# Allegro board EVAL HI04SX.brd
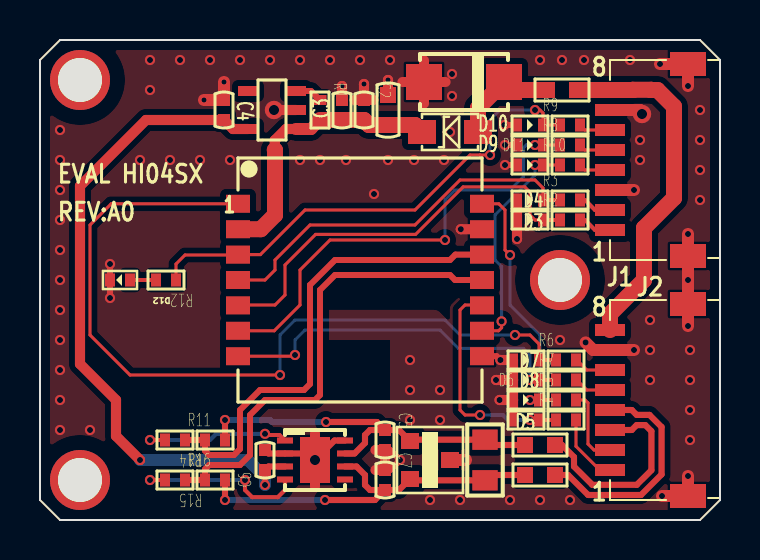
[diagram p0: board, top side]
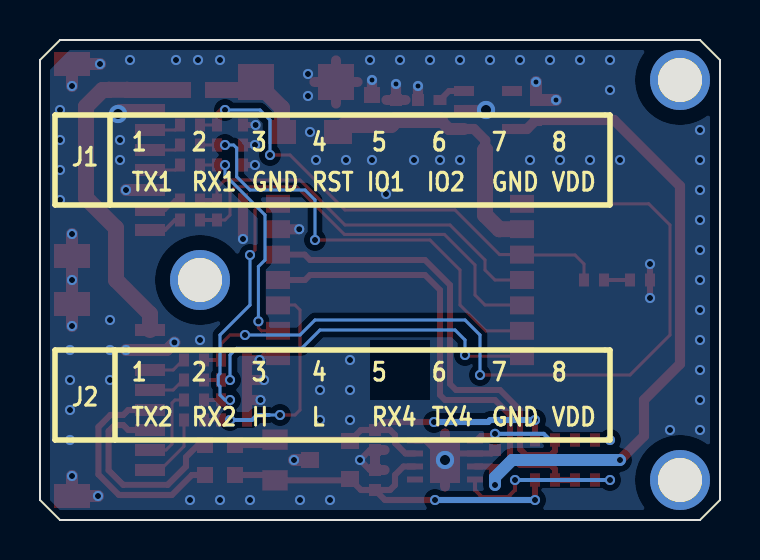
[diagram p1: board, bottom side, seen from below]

Outline 34 x 24 mm; copper layers: TOP, BOTTOM. Coordinates in mm from the lower left corner of the outline.
Outline path: 0,23 0,1 1,0 33,0 34,1 34,23 33,24 1,24 0,23

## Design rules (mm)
constraint set DEFAULT: min track width 0.152
net group CAN2: nets H L

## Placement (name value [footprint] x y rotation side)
C1  10uF  [C0603]  17.4 20.5 270 top
C2  0.1uF  [C0402]  16.2 20.5 270 top
C3  1uF  [C0402]  15.1 20.5 90 top
C4  1uF  [C0402]  9.2 20.5 270 top
C5  100pF  [C0402]  17.25 4 270 top
C6  0.1uF  [C0402]  11.25 3 90 top
C7  100pF  [C0402]  17.25 2 270 top
D1  RB160MM-60TR  [SOD123FL]  20.5 19.4 0 top
D2  SDD32A05L01  [DO-214AC]  21.2 21.9 180 top
D3  SBD52C05L01  [SOD-523]  24.5 15 0 top
D4  SBD52C05L01  [SOD-523]  24.5 16 0 top
D5  SBD52C05L01  [SOD-523]  24.3 5 0 top
D6  SBD52C05L01  [SOD-523]  24.3 6 0 top
D7  SBD52C05L01  [SOD-523]  24.3 8 0 top
D8  SBD52C05L01  [SOD-523]  24.3 7 0 top
D9  SBD52C05L01  [SOD-523]  24.5 18.75 0 top
D10  SBD52C05L01  [SOD-523]  24.5 19.75 0 top
D11  SBD52C05L01  [SOD-523]  24.5 17.75 0 top
D12  GREEN  [LED0402]  4 12 180 top
D13  SM24CANB-02HTG  [SOT23-3-0_95]  19.5 3 270 top
F1  100mA  [F0603]  25 3.75 180 top
F2  100mA  [F0603]  25 2.25 180 top
F3  300mA  [F0603]  26.1 21.5 180 top
H1  HOLE  [HOLE-2-MM]  2 22 0 top
H2  HOLE  [HOLE-2-MM]  2 2 0 top
H3  HOLE  [HOLE-2-MM]  26 12 0 top
J1  CON10  [5015680807_1]  28.5 18 270 top
J2  CON10  [5015680807_1]  28.5 6 270 top
R1  1K  [R0402]  14 20.5 270 top
R2  33R  [R0402]  26.5 15 0 top
R3  33R  [R0402]  26.5 16 0 top
R4  33R  [R0402]  26.3 5 0 top
R5  33R  [R0402]  26.3 6 0 top
R6  33R  [R0402]  26.3 8 0 top
R7  33R  [R0402]  26.3 7 0 top
R8  33R  [R0402]  26.5 18.75 0 top
R9  33R  [R0402]  26.5 19.75 0 top
R10  33R  [R0402]  26.5 17.75 0 top
R11  0R  [R0402]  8.75 4 0 top
R12  1K  [R0402]  6.3 12 180 top
R13  120R/DNP  [R0805]  22.25 3 90 top
R14  1K  [R0402]  6.75 4 180 top
R15  1K  [R0402]  6.75 2 180 top
R16  0R  [R0402]  8.75 2 0 top
U1  SPX3819M5-L-3-3/TR  [SOT23-5-0_95]  11.6 20.5 90 top
U2  HI04SX  [HI04XX]  16 12 0 top
U3  SIT3051TK  [HVSON8]  13.75 3 0 top

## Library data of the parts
C1-C7 = Capacity_Nonpolarity
D1 = diode
D2-D11 = DIODE BI-DIR TRIG
D12 = LED
D13 = BAT54A/SOT
F1-F3 = Fuse
H1-H3 = HOLE
J1 J2 = CON10
R1-R16 = Res
U1 = XC6210
U2 = HI04SX
U3 = SIT3051TK

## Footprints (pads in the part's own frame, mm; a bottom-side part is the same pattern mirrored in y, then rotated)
5015680807_1
  rect 0.6x1.5 smd: 1(3.5,0) 2(2.5,0) 3(1.5,0) 4(0.5,0) 5(-0.5,0) 6(-1.5,0) 7(-2.5,0) 8(-3.5,0)
  rect 1.2x1.8 smd: 9(4.8,3.9) 10(-4.8,3.9)
C0402
  rect 0.6x0.6 smd: 1(-0.5,0) 2(0.5,0)
C0603
  rect 0.8x0.8 smd: 1(-0.75,0) 2(0.75,0)
DO-214AC
  rect 1.8x1.8 smd: 1(2,0) 2(-2,0)
F0603
  rect 0.8x0.8 smd: 1(-0.75,0) 2(0.75,0)
HI04XX
  rect 1.2x0.9 smd: 1(-6.1,3.81) 2(-6.1,2.54) 3(-6.1,1.27) 4(-6.1,0) 5(-6.1,-1.27) 6(-6.1,-2.54) 7(-6.1,-3.81) 8(6.1,-3.81) 9(6.1,-2.54) 10(6.1,-1.27) 11(6.1,0) 12(6.1,1.27) 13(6.1,2.54) 14(6.1,3.81)
HOLE-2-MM
  round 3 hole 2.2: 1(0,0)
HVSON8
  rect 0.8x0.3 smd: 1(-1.5,0.975) 2(-1.5,0.325) 3(-1.5,-0.325) 4(-1.5,-0.975) 5(1.5,-0.975) 6(1.5,-0.325) 7(1.5,0.325) 8(1.5,0.975)
  rect 1.5x2.3 smd: 9(0,0)
LED0402
  rect 0.5x0.65 smd: 1(-0.5,0) 2(0.5,0)
R0402
  rect 0.5x0.65 smd: 1(-0.5,0) 2(0.5,0)
R0805
  rect 1.016x1.27 smd: 1(-1.016,0) 2(1.016,0)
SOD123FL
  rect 1.4x1.2 smd: 1(1.4,0) 2(-1.4,0)
SOD-523
  rect 0.5x0.65 smd: 1(-0.65,0) 2(0.65,0)
SOT23-3-0_95
  rect 0.8x0.9 smd: 1(-0.95,-1) 2(0.95,-1) 3(0,1)
SOT23-5-0_95
  rect 0.5x1 smd: 1(-0.95,-1.2) 2(0,-1.2) 3(0.95,-1.2) 4(0.95,1.2) 5(-0.95,1.2)

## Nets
GND: C1.1 C2.1 C3.2 C4.1 C5.2 C6.2 C7.1 D2.1 D3.1 D4.1 D5.1 D6.1 D7.1 D8.1 D9.1 D10.1 D11.1 D12.2(-) D13.3 J1.3 J1.7 J1.9 J1.10 J2.7 J2.9 J2.10 U1.2(VSS) U2.8 U2.13 U3.2 U3.8 U3.9
VCC: F3.1 J1.8 J2.8
VDD: C1.2 C2.2 C3.1 D1.2 R1.2 U1.1 U2.2(VDD)
CAN_RX/L: R15.1 R16.1 U2.11
CAN_TX/H: R11.1 R14.1 U2.12
DP3V3: C4.2 C6.1 U1.5 U3.3(VCC)
H: F1.1 J2.3
IO1: D9.2 R8.1 U2.6
IO2: D10.2 R9.1 R12.1 U2.3
IO_1: J1.5 R8.2
IO_2: J1.6 R9.2
L: F2.1 J2.4
NRST: J1.4 R10.2
RST: D11.2 R10.1 U2.9
RXD1: D4.2 R3.1 U2.4
RXD2: D6.2 R5.1 U2.14
RXD4: D8.2 R7.1 U2.7
TXD1: D3.2 R2.1 U2.5
TXD2: D5.2 R4.1 U2.10
TXD4: D7.2 R6.1 U2.1
USART1_RX: J1.2 R3.2
USART1_TX: J1.1 R2.2
USART2_RX: J2.2 R5.2
USART2_TX: J2.1 R4.2
USART4_RX: J2.5 R7.2
USART4_TX: J2.6 R6.2
N2198535: D12.1 R12.2
N2224750: R1.1 U1.3
N2242059: C5.1 D13.1 F1.2 R11.2 R13.2 U3.7
N2242241: R14.2 U3.1
N2242331: C7.2 D13.2 F2.2 R13.1 R16.2 U3.6
N2242381: R15.2 U3.4
N2269430: D1.1(P) D2.2 F3.2

Pads without a net: H1 1; H2 1; H3 1; U1 4; U3 5

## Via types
v1: diameter 0.508, hole 0.305, TOP to BOTTOM, 110 vias
v2: diameter 0.508, hole 0.254, TOP to BOTTOM, 5 vias
v3: diameter 0.914, hole 0.508, TOP to BOTTOM, 3 vias

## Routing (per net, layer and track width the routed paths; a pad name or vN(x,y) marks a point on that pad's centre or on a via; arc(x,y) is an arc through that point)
GND: length 50
  TOP w0.3: v1(23.02,8) 22.83,8.19 U2.8 ; D9.1 v1(23.25,18.75) ; D10.1 v1(23.22,19.75) ; D11.1 v1(23.25,17.75)
  TOP w0.305: C5.2 17.5,3.5 v1(18,3) 17.5,2.5 C7.1 ; U3.8 14.72,3.97 v3(13.75,3) 13.43,3.32 U3.2 11.43,3.32 C6.2 ; v1(3.5,11.1) D12.2 v1(3.5,12.8)
  TOP w0.5: 18.12,21.9 D2.1 ; D2.1 20.28,21.9 ; D2.1 19.2,22.98 ; D2.1 19.2,20.82 ; 13.75,1.67 v3(13.75,3) 13.75,4.33 ; 15.72,21 C2.1 16.68,21 ; 17.25,2.98 C7.1 16.77,2.5 ; 16.77,3.5 C5.2 17.25,3.02
  TOP w0.508: D5.1 D6.1 ; D6.1 v1(22.98,6) ; D6.1 D8.1 ; D8.1 v1(22.8,7) ; D8.1 D7.1 v1(23.02,8) ; C3.2 v2(15.1,21.7) ; U1.2 v3(11.7,20.5) ; v1(23.85,14.05) D3.1 D4.1 ; U2.13 v1(21.04,14.54) ; C1.1 v2(17.4,22) ; C2.1 v2(16.2,21.8)
  TOP w0.6: v1(31,22.8) J1.10 v1(32.4,21.7) ; v2(9.2,21.9) C4.1 v2(8.2,21) ; v3(30.1,20.3) 30.1,20.4 30,20.5 J1.7 ; v1(32.4,14.3) J1.9 v1(32.4,12) J2.10 v1(32.4,9.7) ; v1(31.1,1.2) J2.9 v1(32.4,2.2) ; v1(27.28,8.88) 27.66,8.5 J2.7 v1(29.7,8.5) ; J1.3 v1(29.7,16.5) ; D13.3 v1(21.3,3)
  vias: v1(1,19.5) v1(1,18) v1(1,16.5) v1(1,15) v1(1,13.5) v1(1,12) v1(1,10.5) v1(1,9) v1(1,7.5) v1(1,6) v1(1,4.5) v1(2.5,4.5) v1(5,18) v1(5.5,23) v1(5.5,21.5) v1(6.5,18) v1(7,23) v1(8,18) v1(8.5,23) v1(9.5,18) v1(10,23) v1(11.5,23) v1(13,23) v1(13,18) v1(14,18) v1(14.5,23) v1(15.3,18) v1(16,23) v1(16.7,16.3) v1(17.4,18) v1(17.5,23) v1(18.5,8) v1(18.5,6.5) v1(18.5,5) v1(18.7,18) v1(19.5,1) v1(20,6.5) v1(20,5) v1(20.2,18) v1(20.5,19.4) v1(20.6,22.3) v1(20.6,21.2) v1(21,1) v1(23.5,1) v1(25,23) v1(25,1) v1(26,9) v1(26.1,23) v1(26.5,1) v1(27.2,23) v1(29.5,23) v1(30,19) v1(30,18) v1(30.5,10) v1(30.5,8.5) v1(30.5,7) v1(32.5,8.5) v1(32.5,7) v1(32.5,5.5) v1(32.5,4) v1(33,20.5) v1(33,19) v1(33,17.5) v1(33,16)
VCC: length 17.7
  TOP w0.8: J2.8 28.5,10.3 30.2,12 30.2,14.6 31.7,16.1 31.7,20.67 30.87,21.5 30.57,21.5 30.56,21.51 29.64,21.51 29.63,21.5 J1.8 F3.1
VDD: length 13.9
  TOP w0.508: 11.74,18.5 11.74,18.99 12.3,19.55 U1.1
  TOP w0.6: U1.1 13.55,19.55 R1.2
  TOP w0.8: D1.2 18.75,19.75 C1.2 16.45,19.75 C2.2 C3.1 R1.2 ; 11.74,18.5 11.75,18.49 11.75,15.25 11.04,14.54 U2.2
CAN_RX/L: length 23.8
  TOP w0.3: U2.11 20.75,12 20.5,12.25 14.75,12.25 14,11.5 14,6.25 13.75,6 11.25,6 10.5,5.25 10.5,3.25 10,2.75 8.46,2.75 8.25,2.54 R16.1
  TOP w0.305: R16.1 R15.1
CAN_TX/H: length 23.7
  TOP w0.3: U2.12 20.77,13.27 20.5,13 14.75,13 13.5,11.75 13.5,6.8 13.2,6.5 11,6.5 10,5.5 10,3.55 9.7,3.25 8.46,3.25 8.25,3.46 R11.1
  TOP w0.305: R14.1 R11.1
DP3V3: length 33.7
  TOP w0.305: U3.3 11.43,2.68 C6.1 v1(11.25,1.75)
  TOP w0.508: v1(5,3) 3.8,4.2 3.8,6 2,7.8 2,16.7 5.3,20 C4.2 9.65,19.55 U1.5
  BOTTOM w0.6: v1(11.25,1.75) 11.25,2.14 10.39,3 v1(5,3)
H: length 10.5
  TOP w0.305: J2.3 29.59,4.5 29.83,4.75 30.27,4.75 30.57,4.44 30.57,2.49 29.84,1.76 27.62,1.76 26.7,2.68 26.7,3.15 26.1,3.75 F1.1
IO1: length 23
  TOP w0.152: U2.6 11.71,9.46 13,10.75 13,12.5 14.5,14 v1(20.25,14) ; v1(24.75,18.75) D9.2 R8.1
  BOTTOM w0.152: v1(24.75,18.75) 24.32,18.75 24.17,18.6 24.17,17.17 23.5,16.5 20.75,16.5 20.25,16 v1(20.25,14)
IO2: length 24.9
  TOP w0.152: v1(24.75,20.5) 25,20.5 25.15,20.35 D10.2 R9.1 ; v1(22.5,18.25) 22,18.25 21.5,18.25 18.75,15.5 13.25,15.5 11.02,13.27 U2.3 9.88,13.25 7.25,13.25 6.8,12.8 R12.1
  BOTTOM w0.152: v1(24.75,20.5) 23,20.5 22.5,20 v1(22.5,18.25)
IO_1: length 1.6
  TOP w0.152: R8.2 27.25,18.5 J1.5
IO_2: length 1.6
  TOP w0.152: J1.6 27.25,19.5 R9.2
L: length 11.5
  TOP w0.305: F2.1 26.41,2.25 27.41,1.25 30.05,1.25 31.08,2.28 31.08,4.65 30.48,5.25 29.83,5.25 29.59,5.5 J2.4
NRST: length 1.6
  TOP w0.152: J1.4 27.25,17.5 R10.2
RST: length 11.4
  TOP w0.152: v1(24.75,17.75) D11.2 R10.1 ; v1(23.08,9.93) 23.08,9.61 22.93,9.46 U2.9
  BOTTOM w0.152: v1(24.75,17.75) 24.75,17.25 22.75,15.25 22.75,13 23.08,12.67 v1(23.08,9.93)
RXD1: length 19.2
  TOP w0.152: D4.2 25.15,16.6 24.75,17 21,17 18.75,14.75 13.5,14.75 11.75,13 11.75,12.5 11.25,12 U2.4
  TOP w0.203: R3.1 D4.2
RXD2: length 13.2
  TOP w0.152: U2.14 22.94,15.81 23.25,15.5 23.25,13.5 v1(23.5,13.25) ; v1(24.5,6) D6.2
  TOP w0.203: R5.1 D6.2
  BOTTOM w0.152: v1(24.5,6) 24.75,6 25,6.25 25,6.67 25.08,6.76 25.08,7.24 25,7.33 25,9.25 23.5,10.75 v1(23.5,13.25)
RXD4: length 18.6
  TOP w0.152: v1(12.75,8.25) 12.69,8.19 U2.7 ; D8.2 v1(24.5,7)
  TOP w0.203: R7.1 D8.2
  BOTTOM w0.152: v1(24.5,7) 24.5,8.25 24.17,8.58 20.92,8.58 20,9.5 13.25,9.5 12.75,9 v1(12.75,8.25)
TXD1: length 20.8
  TOP w0.152: U2.5 9.92,10.75 11.75,10.75 12.25,11.25 12.25,12.75 13.78,14.28 18.78,14.28 21.16,16.66 24.24,16.66 24.5,16.39 24.5,15.25 24.75,15 D3.2
  TOP w0.203: D3.2 R2.1
TXD2: length 11.2
  TOP w0.152: v1(22,5.25) 21.25,5.25 21,5.5 21,10.5 21.25,10.75 22.08,10.75 U2.10
  TOP w0.203: R4.1 D5.2 v1(24.5,5)
  BOTTOM w0.152: v1(22,5.25) 22.55,5.25
  BOTTOM w0.203: v1(24.5,5) 23.4,5 23.15,5.25 22.55,5.25
TXD4: length 41.1
  TOP w0.152: U2.1 3.56,15.81 2.5,14.75 2.5,9.25 4.5,7.25 v1(12,7.25) ; D7.2 24.95,8.8 24.5,9.25 v1(23.75,9.25)
  TOP w0.203: R6.1 D7.2
  BOTTOM w0.152: v1(12,7.25) 12,9.25 12.75,10 20.25,10 21,9.25 v1(23.75,9.25)
USART1_RX: length 1.7
  TOP w0.203: J1.2 27.75,15.5 27.25,16 R3.2
USART1_TX: length 1.7
  TOP w0.203: J1.1 27.75,14.5 27.25,15 R2.2
USART2_RX: length 3.9
  TOP w0.152: J2.2 27.7,3.5 27.4,3.8 27.4,5.85 27.25,6 R5.2
USART2_TX: length 3.5
  TOP w0.152: J2.1 27.98,2.5 26.8,3.68 R4.2
USART4_RX: length 1.9
  TOP w0.152: R7.2 26.84,7 27.34,6.5 J2.5
USART4_TX: length 1.9
  TOP w0.152: R6.2 26.84,8 27.34,7.5 J2.6
N2198535: length 1.3
  TOP w0.203: R12.2 D12.1
N2224750: length 1.4
  TOP w0.3: U1.3 13.55,21.45 R1.1
N2242059: length 19.3
  TOP w0.305: v1(9.25,5) R11.2 ; v1(14.3,4.9) 16.85,4.9 C5.1 ; F1.2 22.52,3.75 R13.2 18.57,4.02 D13.1 17.95,4.5 C5.1 ; C5.1 16.5,4.5 16.25,4.25 16.25,3.85 15.72,3.32 U3.7
  BOTTOM w0.305: v1(14.3,4.9) 11.59,4.9 11.49,5 v1(9.25,5)
N2242241: length 7.8
  TOP w0.203: R14.2 v1(5.5,4) ; v1(11.25,4.31) 11.31,4.25 11.97,4.25 U3.1
  BOTTOM w0.203: v1(11.25,4.31) 8.81,4.31 8.5,4 v1(5.5,4)
N2242331: length 19.4
  TOP w0.305: v1(14.25,1) 16.75,1 C7.2 ; U3.6 15.82,2.68 16.25,2.25 16.25,1.75 16.5,1.5 C7.2 ; C7.2 17.95,1.5 D13.2 18.57,1.98 R13.1 22.52,2.25 F2.2 ; v1(9.25,1) R16.2
  BOTTOM w0.305: v1(14.25,1) v1(9.25,1)
N2242381: length 8.8
  TOP w0.203: U3.4 12.25,1.5 11.89,1.14 10.61,1.14 10.25,1.5 v1(10.25,2) ; R15.2 v1(5.5,2)
  BOTTOM w0.203: v1(5.5,2) v1(10.25,2)
N2269430: length 5.4
  TOP w0.8: F3.2 23.6,21.5 D2.2 21.9,20.6 D1.1

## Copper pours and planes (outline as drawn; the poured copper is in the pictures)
GND on TOP: 1.5,23.5 32.5,23.5 33.5,22.5 33.5,1 33,0.5 1.5,0.5 0.5,1.5 0.5,22.5 ; 13 cut-outs
GND on TOP: 1.5,23.5 32.5,23.5 33.5,22.5 33.5,1 33,0.5 1.5,0.5 0.5,1.5 0.5,22.5 ; 13 cut-outs
GND on BOTTOM: 1.5,23.5 32.5,23.5 33.5,22.5 33.5,1 33,0.5 1.5,0.5 0.5,1.5 0.5,22.5
GND on BOTTOM: 1.5,23.5 32.5,23.5 33.5,22.5 33.5,1 33,0.5 1.5,0.5 0.5,1.5 0.5,22.5 ; 1 cut-out

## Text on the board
Ref Des/Silkscreen Bottom: 8 | VDD | 7 | GND | 6 | TX4 | IO2 | 5 | RX4 | IO1 | 4 | RST | L | 3 | H | 2 | RX1 | RX2 | 1 | TX1 | TX2 | J1 | J2
Ref Des/Silkscreen Top: EVAL HI04SX | REV:A0 | 8 | 1 | J1 | J2
User.8: FIGURE | FINISHED_SIZE | 10.0 | 12.0 | 20.0 | 86.614 | DRILL CHART: TOP to BOTTOM | ALL UNITS ARE IN MILS | PLATED | QTY | 126 | 2 | 3
